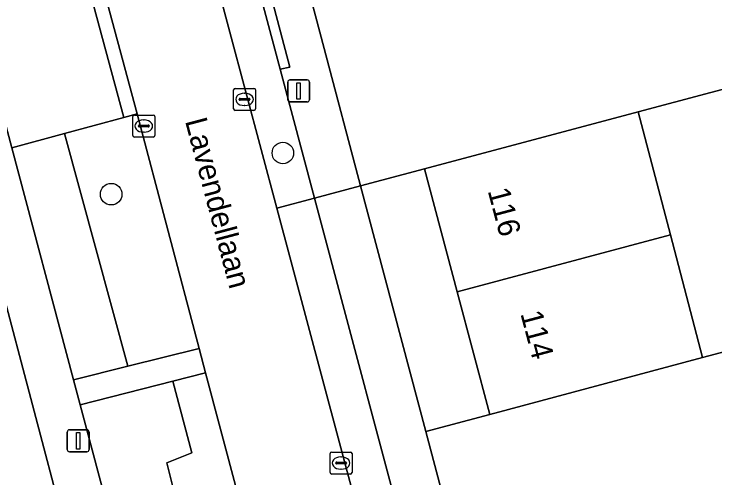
# Model space of a CAD drawing. Extents: x 162542 to 163147, y 380779 to 381521.
# Drawn here: x 162637.43 to 162669.28, y 381131.79 to 381152.86 of the extents above; entities that cross this region are included whole.
import ezdxf

# ---------------------------------------------------------------- set-up
doc = ezdxf.new("R2010")
doc.units = 0
for name, color, linetype in [('IMGEO_Boom', 7, 'Continuous'), ('IMGEO_Erf', 7, 'Continuous'), ('IMGEO_Groenvoorziening', 7, 'Continuous'), ('IMGEO_Kolk', 7, 'Continuous'), ('IMGEO_Lichtmast', 7, 'Continuous'), ('IMGEO_Openbare_ruimte_label', 7, 'Continuous'), ('IMGEO_Pand', 7, 'Continuous'), ('IMGEO_Pand_nummerreeks', 7, 'Continuous'), ('IMGEO_Parkeervlak_open', 7, 'Continuous'), ('IMGEO_Rijbaan_lokaal_open', 7, 'Continuous'), ('IMGEO_Voetpad_open', 7, 'Continuous')]:
    doc.layers.add(name, color=color, linetype=linetype)

msp = doc.modelspace()

# ---------------------------------------------------------------- linework, layer by layer
at = {"layer": 'IMGEO_Boom'}
for centre in [(162649.65, 381146.551), (162641.848, 381144.68)]:
    msp.add_circle(centre, 0.489, dxfattribs=at)
at = {"layer": 'IMGEO_Erf'}
for points in [[(162678.692, 381144.15), (162677.911, 381147.157), (162674.943, 381146.367), (162673.828, 381150.554), (162665.799, 381148.416), (162667.262, 381142.828), (162668.718, 381137.261), (162676.798, 381139.397), (162675.742, 381143.365)], [(162653.181, 381145.057), (162656.145, 381133.899), (162659.049, 381134.67), (162657.565, 381140.248), (162656.081, 381145.826)], [(162639.746, 381129.54), (162636.792, 381140.677), (162633.868, 381139.932), (162635.326, 381134.447), (162636.835, 381128.769)]]:
    msp.add_lwpolyline(points, close=True, dxfattribs=at)
at = {"layer": 'IMGEO_Groenvoorziening'}
for points in [[(162643.024, 381148.328), (162642.421, 381148.163), (162639.72, 381147.43), (162642.612, 381136.866), (162645.846, 381137.677)], [(162639.72, 381147.43), (162637.327, 381146.78), (162640.133, 381136.243), (162642.612, 381136.866)], [(162646.141, 381136.563), (162644.655, 381136.184), (162645.512, 381132.926), (162644.373, 381132.48), (162645.568, 381127.699), (162647.414, 381128.192), (162648.065, 381125.594), (162648.385, 381125.691), (162648.974, 381125.871)], [(162644.655, 381136.184), (162640.435, 381135.109), (162643.311, 381124.312), (162646.229, 381125.075), (162645.568, 381127.699), (162644.373, 381132.48), (162645.512, 381132.926)]]:
    msp.add_lwpolyline(points, close=True, dxfattribs=at)
at = {"layer": 'IMGEO_Kolk'}
for p, q in [((162647.408, 381148.562), (162647.408, 381149.414)), ((162647.483, 381149.488), (162648.335, 381149.488)), ((162648.409, 381149.414), (162648.409, 381148.562)), ((162647.896, 381149.268), (162647.921, 381149.268)), ((162647.667, 381148.982), (162647.667, 381148.994)), ((162648.105, 381148.945), (162647.707, 381148.945)), ((162647.71, 381149.031), (162648.108, 381149.031)), ((162648.151, 381148.994), (162648.151, 381148.982)), ((162648.335, 381148.488), (162647.483, 381148.488)), ((162647.919, 381148.708), (162647.894, 381148.708)), ((162642.83, 381147.35), (162642.83, 381148.202)), ((162642.905, 381148.276), (162643.757, 381148.276)), ((162643.831, 381148.202), (162643.831, 381147.35)), ((162643.132, 381147.819), (162643.53, 381147.819)), ((162643.318, 381148.056), (162643.343, 381148.056)), ((162643.089, 381147.77), (162643.089, 381147.782)), ((162643.527, 381147.733), (162643.129, 381147.733)), ((162643.341, 381147.496), (162643.316, 381147.496)), ((162643.573, 381147.782), (162643.573, 381147.77)), ((162643.757, 381147.276), (162642.905, 381147.276)), ((162651.794, 381132.042), (162651.794, 381132.894)), ((162651.869, 381132.968), (162652.721, 381132.968)), ((162652.795, 381132.894), (162652.795, 381132.042)), ((162652.096, 381132.511), (162652.494, 381132.511)), ((162652.282, 381132.748), (162652.307, 381132.748)), ((162652.053, 381132.462), (162652.053, 381132.474)), ((162652.491, 381132.425), (162652.093, 381132.425)), ((162652.305, 381132.188), (162652.28, 381132.188)), ((162652.537, 381132.474), (162652.537, 381132.462)), ((162652.721, 381131.968), (162651.869, 381131.968))]:
    msp.add_line(p, q, dxfattribs=at)
for points in [[(162647.408, 381148.562), (162647.408, 381149.414)], [(162647.483, 381149.488), (162648.335, 381149.488)], [(162648.409, 381149.414), (162648.409, 381148.562)], [(162648.335, 381148.488), (162647.483, 381148.488)], [(162642.83, 381147.35), (162642.83, 381148.202)], [(162642.905, 381148.276), (162643.757, 381148.276)], [(162643.831, 381148.202), (162643.831, 381147.35)], [(162643.757, 381147.276), (162642.905, 381147.276)], [(162651.794, 381132.042), (162651.794, 381132.894)], [(162651.869, 381132.968), (162652.721, 381132.968)], [(162652.795, 381132.894), (162652.795, 381132.042)], [(162652.721, 381131.968), (162651.869, 381131.968)]]:
    msp.add_lwpolyline(points, dxfattribs=at)
for centre, radius, start, end in [((162647.485, 381149.412), 0.0765, 91.552, 178.448), ((162647.485, 381149.412), 0.0765, 91.552, 178.448), ((162648.333, 381149.412), 0.0765, 1.552, 88.448), ((162648.333, 381149.412), 0.0765, 1.552, 88.448), ((162647.707, 381148.991), 0.0403, 85.8775, 175.7526), ((162647.704, 381148.981), 0.0366, 178.938, 274.7102), ((162648.108, 381148.988), 0.043, 264.8664, 352.4533), ((162648.112, 381148.993), 0.0386, 1.7309, 96.639), ((162647.485, 381148.564), 0.0765, 181.552, 268.448), ((162647.485, 381148.564), 0.0765, 181.552, 268.448), ((162648.333, 381148.564), 0.0765, 271.552, 358.448), ((162648.333, 381148.564), 0.0765, 271.552, 358.448), ((162642.907, 381148.2), 0.0765, 91.552, 178.448), ((162642.907, 381148.2), 0.0765, 91.552, 178.448), ((162643.755, 381148.2), 0.0765, 1.552, 88.448), ((162643.755, 381148.2), 0.0765, 1.552, 88.448), ((162643.129, 381147.779), 0.0403, 85.8775, 175.7526), ((162643.534, 381147.781), 0.0386, 1.7309, 96.639), ((162643.126, 381147.769), 0.0366, 178.938, 274.7102), ((162643.53, 381147.776), 0.043, 264.8664, 352.4533), ((162642.907, 381147.352), 0.0765, 181.552, 268.448), ((162642.907, 381147.352), 0.0765, 181.552, 268.448), ((162643.755, 381147.352), 0.0765, 271.552, 358.448), ((162643.755, 381147.352), 0.0765, 271.552, 358.448), ((162651.871, 381132.892), 0.0765, 91.552, 178.448), ((162651.871, 381132.892), 0.0765, 91.552, 178.448), ((162652.719, 381132.892), 0.0765, 1.552, 88.448), ((162652.719, 381132.892), 0.0765, 1.552, 88.448), ((162652.093, 381132.471), 0.0403, 85.8775, 175.7526), ((162652.498, 381132.473), 0.0386, 1.7309, 96.639), ((162652.09, 381132.461), 0.0366, 178.938, 274.7102), ((162652.494, 381132.468), 0.043, 264.8664, 352.4533), ((162651.871, 381132.044), 0.0765, 181.552, 268.448), ((162651.871, 381132.044), 0.0765, 181.552, 268.448), ((162652.719, 381132.044), 0.0765, 271.552, 358.448), ((162652.719, 381132.044), 0.0765, 271.552, 358.448)]:
    msp.add_arc(centre, radius, start, end, dxfattribs=at)
for centre, major_axis, ratio, start_param, end_param in [((162647.895, 381148.988), (-0.387, 0.002), 0.722429, 4.712389, 7.853982), ((162647.92, 381148.988), (-0.39, 0.002), 0.717154, 1.570796, 4.712389), ((162643.317, 381147.776), (-0.387, 0.002), 0.722429, 4.712389, 7.853982), ((162643.342, 381147.776), (-0.39, 0.002), 0.717154, 1.570796, 4.712389), ((162652.281, 381132.468), (-0.387, 0.002), 0.722429, 4.712389, 7.853982), ((162652.306, 381132.468), (-0.39, 0.002), 0.717154, 1.570796, 4.712389)]:
    msp.add_ellipse(centre, major_axis=major_axis, ratio=ratio, start_param=start_param, end_param=end_param, dxfattribs=at)
at = {"layer": 'IMGEO_Lichtmast'}
for p, q in [((162649.869, 381148.97), (162649.869, 381149.77)), ((162649.869, 381149.77), (162649.869, 381148.97)), ((162649.969, 381149.87), (162650.759, 381149.87)), ((162650.759, 381149.87), (162649.969, 381149.87)), ((162650.859, 381149.77), (162650.859, 381148.97)), ((162650.859, 381148.97), (162650.859, 381149.77)), ((162650.759, 381148.87), (162649.969, 381148.87)), ((162649.969, 381148.87), (162650.759, 381148.87)), ((162639.852, 381133.077), (162639.852, 381133.877)), ((162639.852, 381133.877), (162639.852, 381133.077)), ((162639.952, 381133.977), (162640.742, 381133.977)), ((162640.742, 381133.977), (162639.952, 381133.977)), ((162640.842, 381133.877), (162640.842, 381133.077)), ((162640.842, 381133.077), (162640.842, 381133.877)), ((162640.742, 381132.977), (162639.952, 381132.977)), ((162639.952, 381132.977), (162640.742, 381132.977))]:
    msp.add_line(p, q, dxfattribs=at)
for points in [[(162650.289, 381149.745), (162650.439, 381149.745), (162650.439, 381148.995), (162650.289, 381148.995), (162650.289, 381149.745)], [(162640.272, 381133.852), (162640.422, 381133.852), (162640.422, 381133.102), (162640.272, 381133.102), (162640.272, 381133.852)]]:
    msp.add_lwpolyline(points, dxfattribs=at)
for centre, start, end in [((162649.969, 381149.77), 90, 180), ((162649.969, 381149.77), 90, 180), ((162650.759, 381149.77), 0, 90), ((162650.759, 381149.77), 360, 90), ((162649.969, 381148.97), 180, 270), ((162649.969, 381148.97), 180, 270), ((162650.759, 381148.97), 270, 0), ((162650.759, 381148.97), 270, 0), ((162639.952, 381133.877), 90, 180), ((162639.952, 381133.877), 90, 180), ((162640.742, 381133.877), 0, 90), ((162640.742, 381133.877), 360, 90), ((162639.952, 381133.077), 180, 270), ((162639.952, 381133.077), 180, 270), ((162640.742, 381133.077), 270, 0), ((162640.742, 381133.077), 270, 0)]:
    msp.add_arc(centre, 0.1, start, end, dxfattribs=at)
at = {"layer": 'IMGEO_Pand'}
for points in [[(162671.652, 381169.072), (162666.29, 381167.639), (162664.741, 381173.435), (162652.708, 381170.219), (162654.253, 381164.438), (162648.45, 381162.897), (162651.526, 381151.298), (162653.181, 381145.057), (162656.081, 381145.826), (162665.799, 381148.416), (162673.828, 381150.554), (162676.822, 381151.351), (162676.015, 381154.427), (162675.228, 381157.426), (162673.663, 381163.392), (162673.417, 381163.326), (162671.893, 381169.137)], [(162656.081, 381145.826), (162657.565, 381140.248), (162667.262, 381142.828), (162665.799, 381148.416)], [(162668.718, 381137.261), (162667.262, 381142.828), (162657.565, 381140.248), (162659.049, 381134.67)], [(162684.115, 381122.206), (162684.328, 381122.262), (162682.52, 381129.057), (162682.737, 381129.114), (162681.431, 381133.908), (162681.144, 381134.962), (162680.329, 381137.953), (162679.725, 381140.171), (162676.798, 381139.397), (162668.718, 381137.261), (162659.049, 381134.67), (162656.145, 381133.899), (162657.803, 381127.667), (162660.887, 381116.07), (162666.685, 381117.612), (162668.23, 381111.802), (162680.279, 381114.986), (162678.746, 381120.787)]]:
    msp.add_lwpolyline(points, close=True, dxfattribs=at)
at = {"layer": 'IMGEO_Parkeervlak_open'}
for points in [[(162647.981, 381156.163), (162645.785, 381164.499), (162645.416, 381165.832), (162645.26, 381166.395), (162643.543, 381165.92), (162643.686, 381165.375), (162649.38, 381144.042), (162651.083, 381144.497), (162649.522, 381150.353)], [(162640.636, 381154.797), (162638.324, 381154.112), (162635.59, 381153.303), (162637.327, 381146.78), (162639.72, 381147.43), (162642.421, 381148.163)], [(162651.083, 381144.497), (162649.38, 381144.042), (162657.855, 381112.29), (162659.54, 381112.76), (162657.309, 381121.241), (162655.734, 381127.049)]]:
    msp.add_lwpolyline(points, close=True, dxfattribs=at)
at = {"layer": 'IMGEO_Rijbaan_lokaal_open'}
for points in [[(162658.181, 381110.883), (162657.855, 381112.29), (162649.38, 381144.042), (162643.686, 381165.375)], [(162641.237, 381154.972), (162643.024, 381148.328), (162645.846, 381137.677), (162646.141, 381136.563), (162648.974, 381125.871), (162650.784, 381119.239), (162654.437, 381105.453), (162655.072, 381104.461), (162655.942, 381103.505), (162657.142, 381102.572), (162658.064, 381102.039), (162660.094, 381101.266), (162661.162, 381101.085), (162663.041, 381101.13), (162667.876, 381102.415), (162673.722, 381103.968), (162674.634, 381104.211), (162692.09, 381108.85), (162694.038, 381109.357)]]:
    msp.add_lwpolyline(points, dxfattribs=at)
at = {"layer": 'IMGEO_Voetpad_open'}
for points in [[(162648.45, 381162.897), (162646.862, 381168.708), (162646.164, 381170.751), (162644.195, 381170.241), (162645.26, 381166.395), (162645.416, 381165.832), (162645.785, 381164.499), (162647.981, 381156.163), (162648.438, 381156.257), (162649.973, 381150.456), (162649.522, 381150.353), (162651.083, 381144.497), (162653.181, 381145.057), (162651.526, 381151.298)], [(162645.063, 381117.734), (162643.311, 381124.312), (162640.435, 381135.109), (162640.133, 381136.243), (162637.327, 381146.78), (162635.59, 381153.303), (162633.072, 381162.758), (162632.437, 381164.912), (162630.483, 381164.337), (162632.03, 381158.534), (162635.122, 381146.939), (162636.792, 381140.677), (162639.746, 381129.54), (162641.278, 381123.741), (162644.458, 381111.704), (162646.014, 381105.912), (162648.066, 381106.457)], [(162647.981, 381156.163), (162649.522, 381150.353), (162649.973, 381150.456), (162648.438, 381156.257)], [(162641.237, 381154.972), (162640.636, 381154.797), (162642.421, 381148.163), (162643.024, 381148.328)], [(162646.141, 381136.563), (162645.846, 381137.677), (162642.612, 381136.866), (162640.133, 381136.243), (162640.435, 381135.109), (162644.655, 381136.184)]]:
    msp.add_lwpolyline(points, close=True, dxfattribs=at)
for points in [[(162653.181, 381145.057), (162651.083, 381144.497)], [(162656.145, 381133.899), (162653.181, 381145.057)], [(162651.083, 381144.497), (162655.734, 381127.049)], [(162657.803, 381127.667), (162656.145, 381133.899)]]:
    msp.add_lwpolyline(points, dxfattribs=at)

# ---------------------------------------------------------------- texts
at = {"layer": 'IMGEO_Openbare_ruimte_label'}
msp.add_text('Lavendellaan', height=1, rotation=284.8835, dxfattribs=at).set_placement((162645.198, 381148.01))
at = {"layer": 'IMGEO_Pand_nummerreeks'}
for s, p in [('116', (162658.951, 381144.837)), ('114', (162660.435, 381139.259))]:
    msp.add_text(s, height=1, rotation=284.8987, dxfattribs=at).set_placement(p)

doc.saveas('drawing.dxf')
